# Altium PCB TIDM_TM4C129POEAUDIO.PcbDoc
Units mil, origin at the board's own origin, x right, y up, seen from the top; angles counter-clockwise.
Board outline 2400 x 2000 mil, 4 copper layers (Component Side, Ground Plane, Power Plane, Solder Side), stack 33.234 mil thick; 37 components, 28 nets, 131 pads, 28 vias.
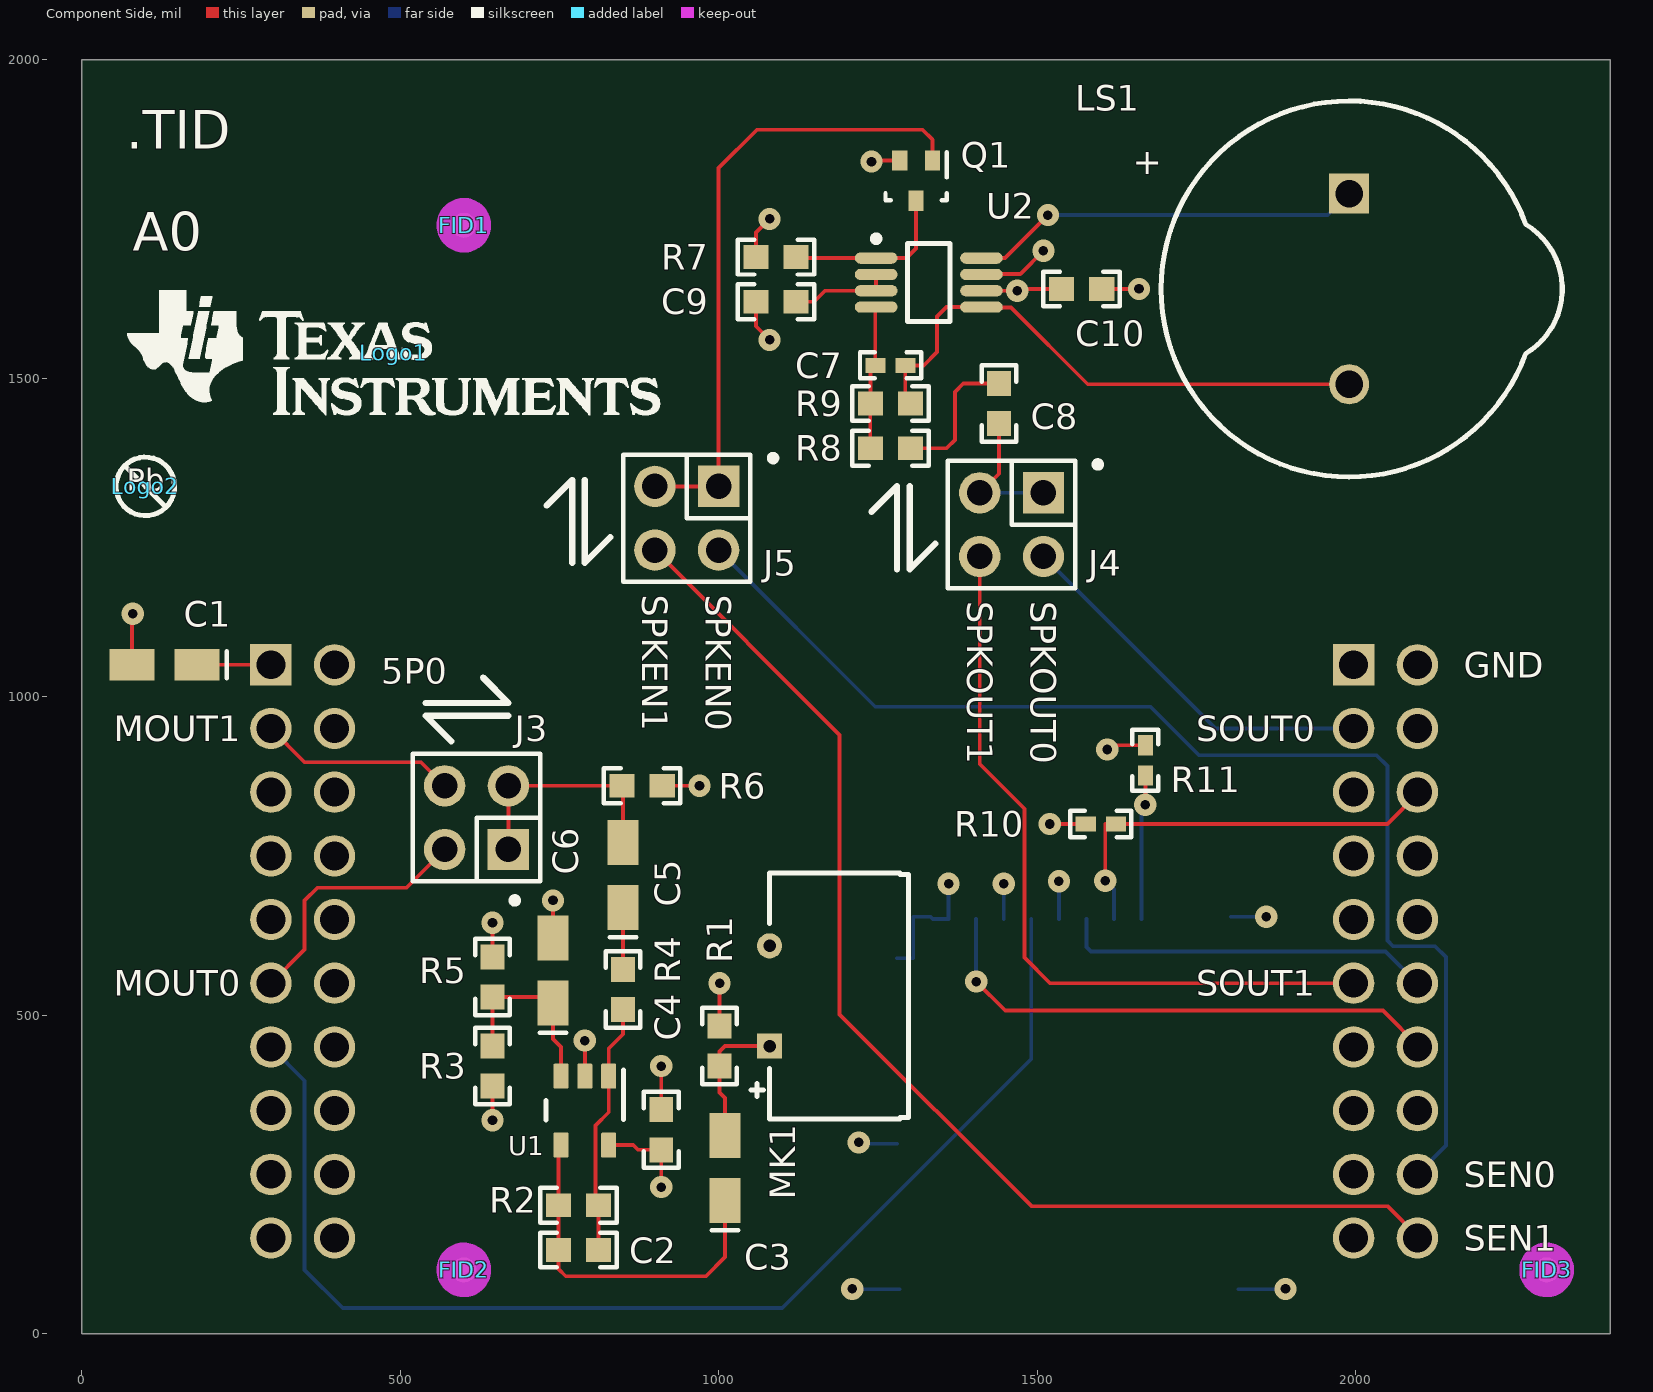
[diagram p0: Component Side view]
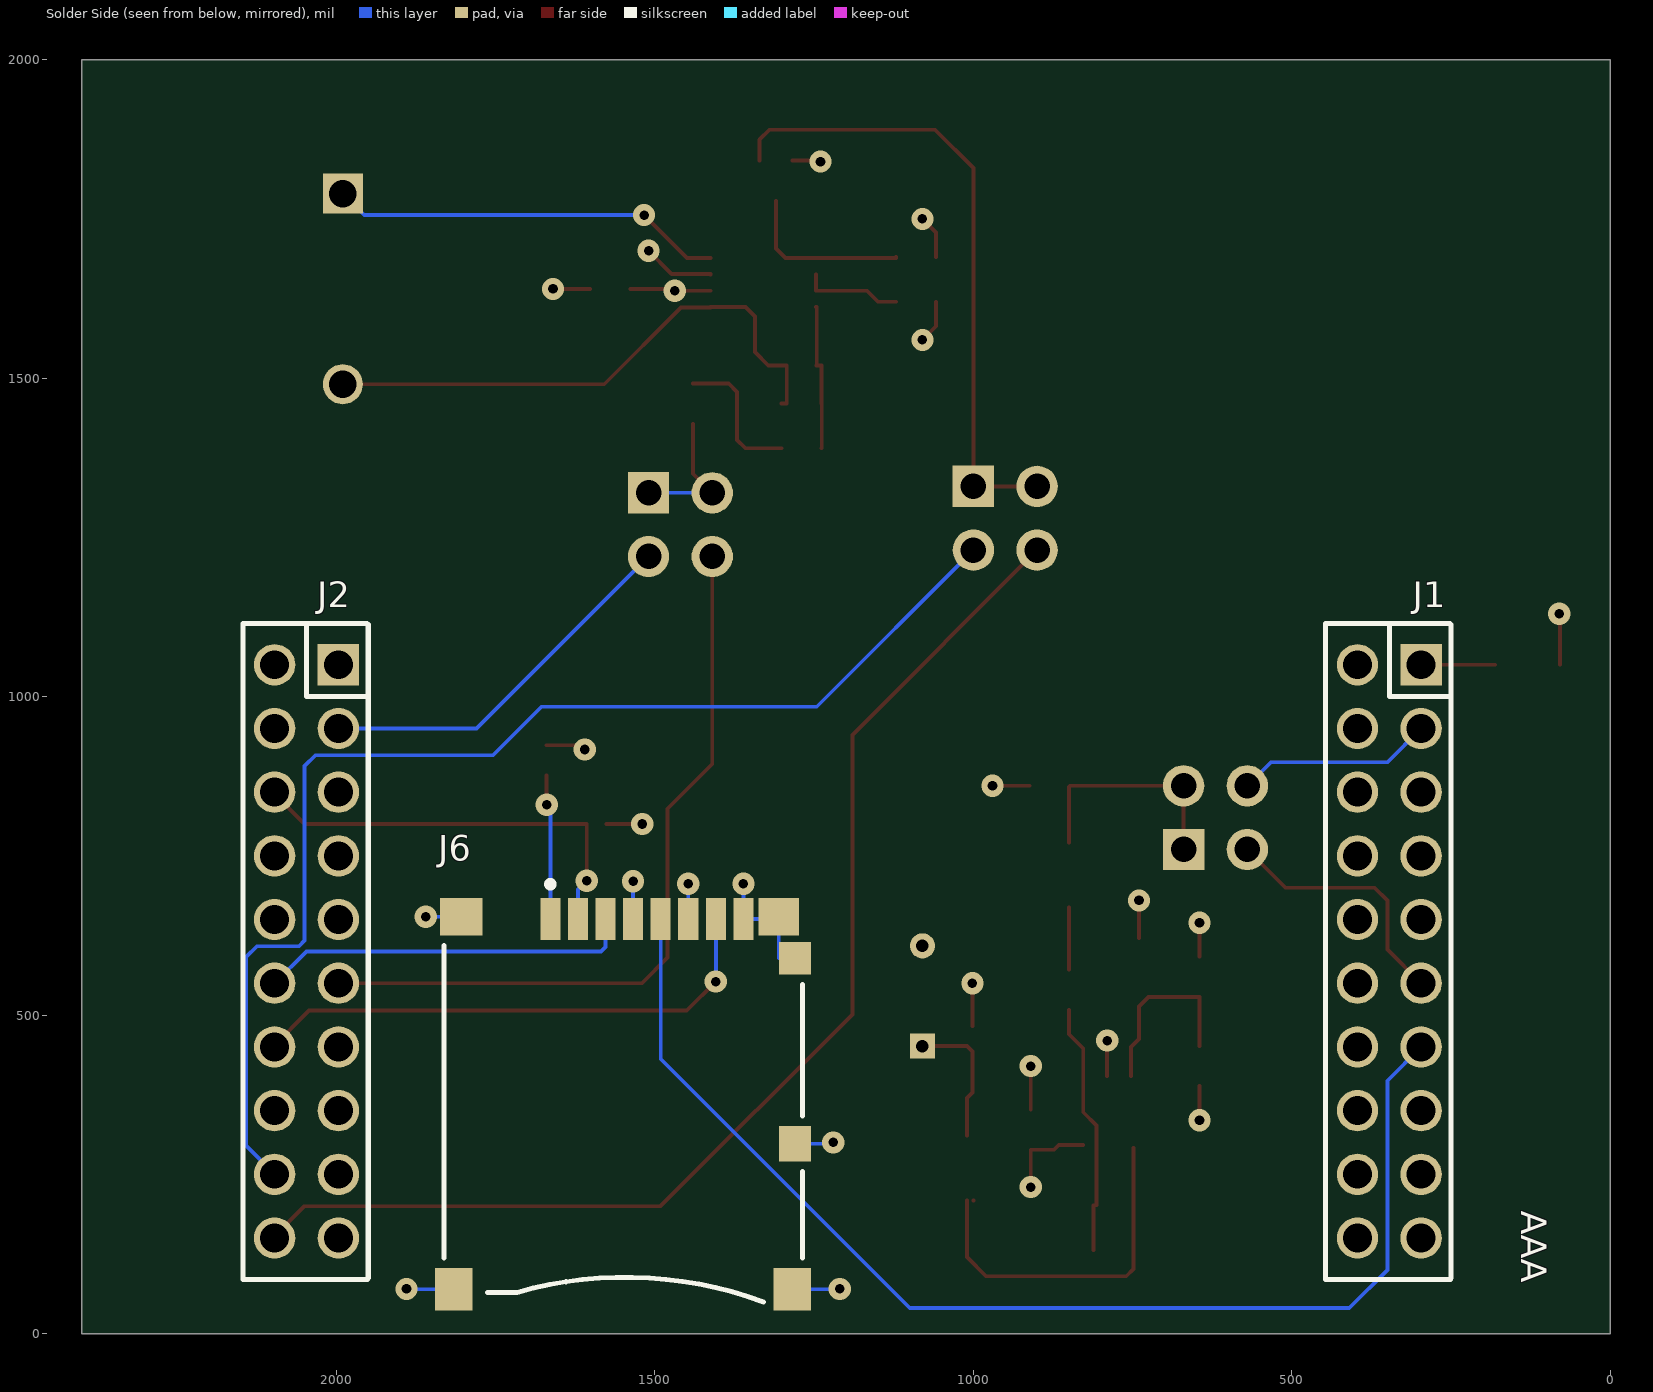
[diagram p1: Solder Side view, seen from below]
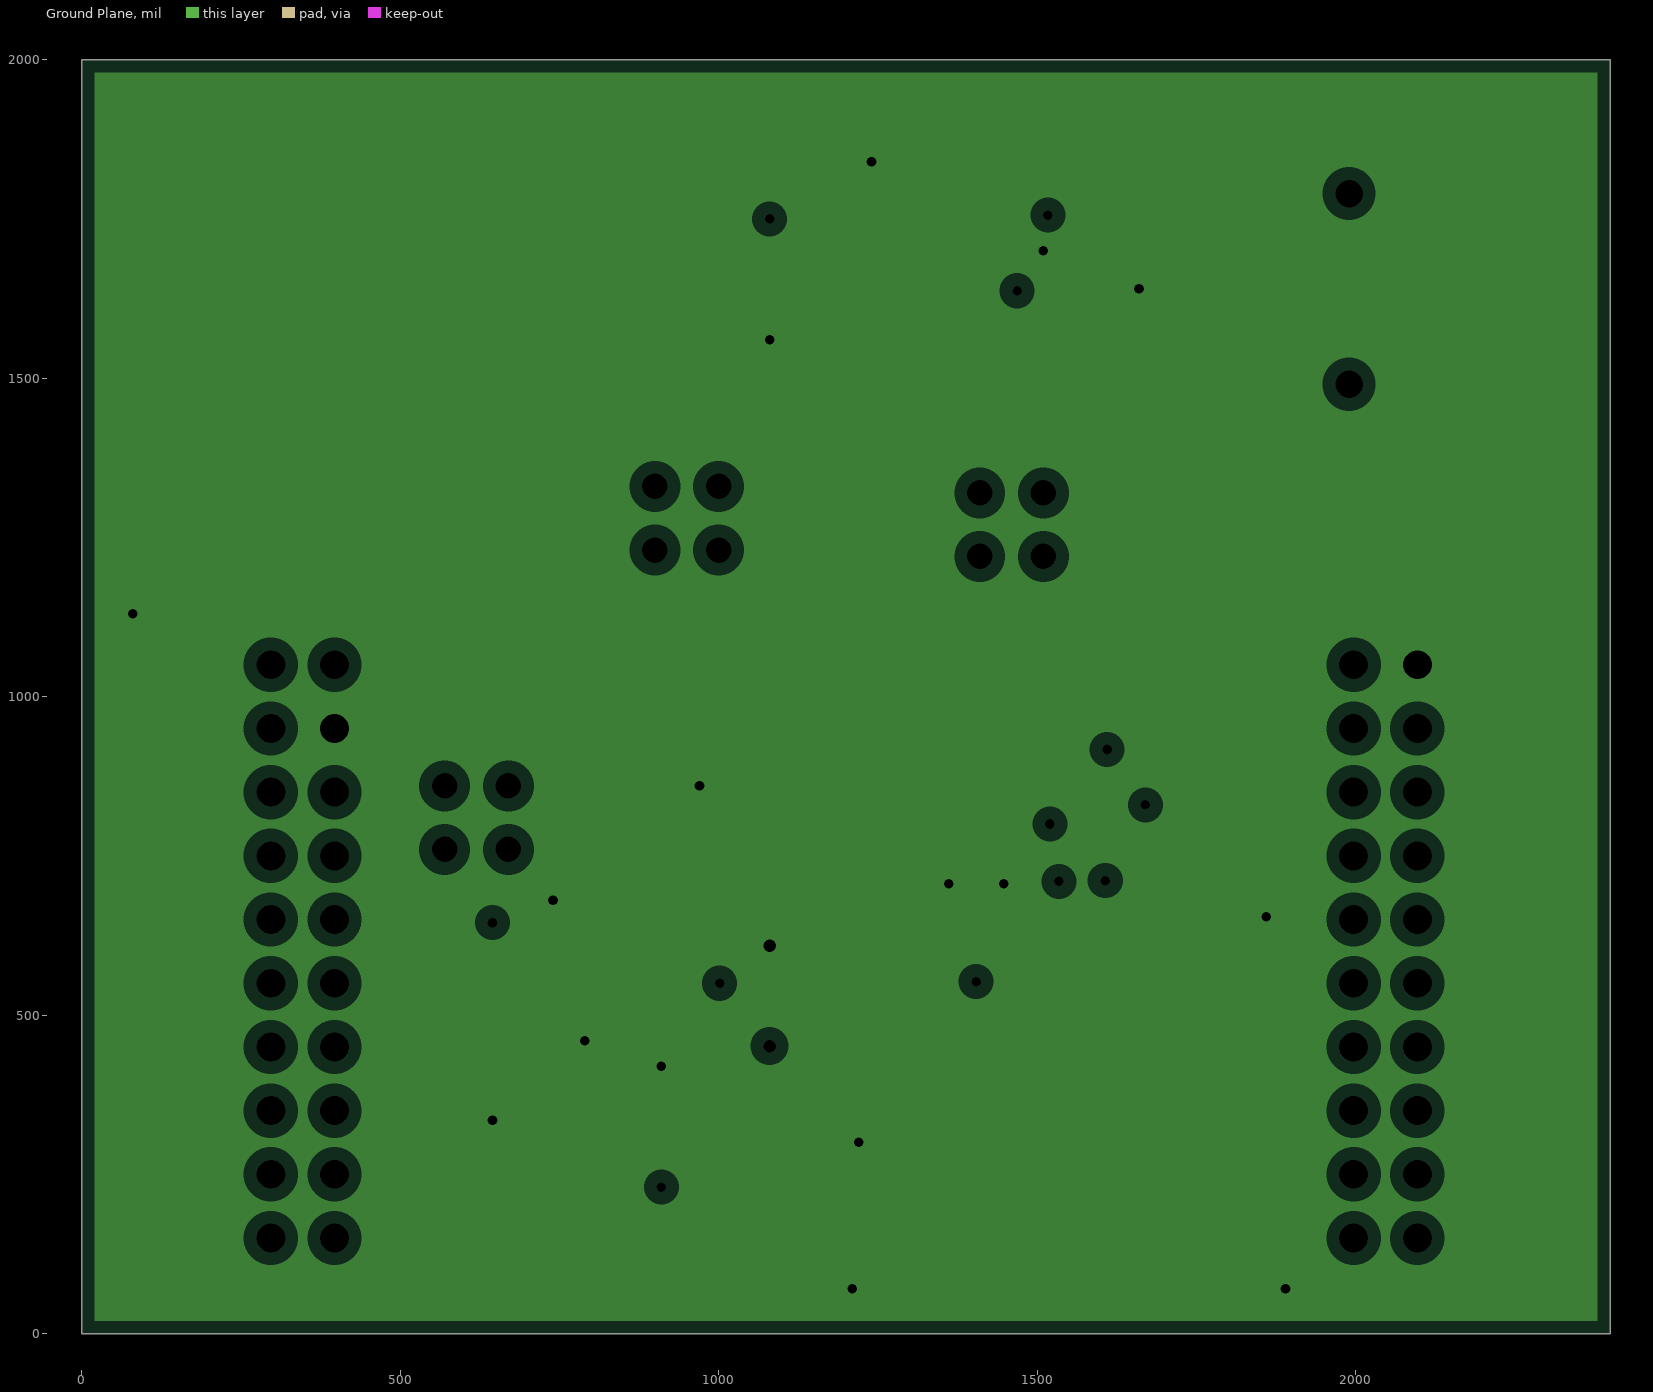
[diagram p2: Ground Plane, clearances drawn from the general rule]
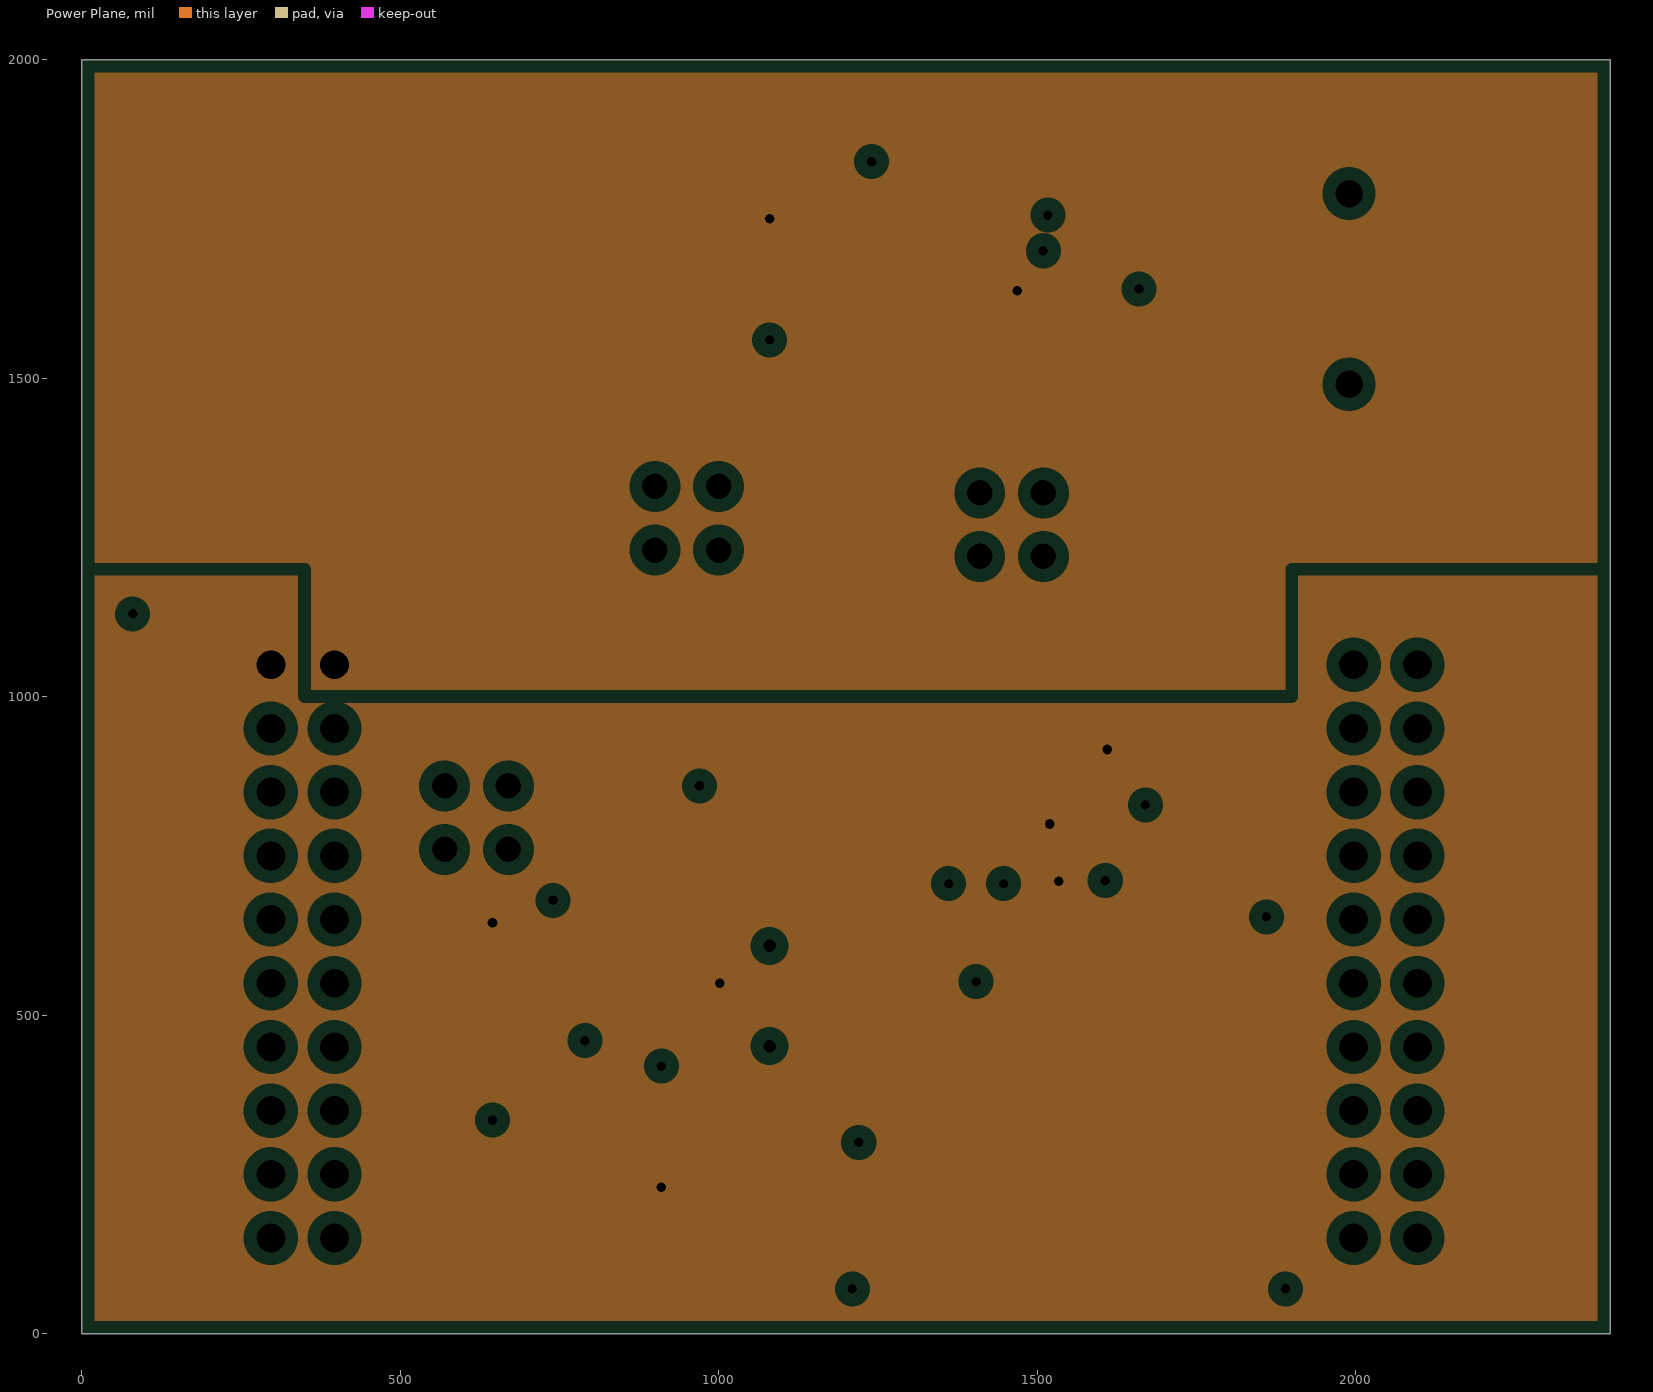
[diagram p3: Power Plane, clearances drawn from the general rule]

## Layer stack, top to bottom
Top Solder: solder mask 0.4, Solder Resist, Dk 3.5
Component Side: signal copper 1.4
Dielectric 1: core 12.6, FR-4, Dk 4.8
Ground Plane: plane copper 1.417, net GND
Dielectric 3: prepreg 5, Dk 4.2
Power Plane: plane copper 1.417, net (Multiple Nets)
Dielectric 4: core 10, Dk 4.2
Solder Side: signal copper 1.4
Bottom Solder: solder mask 0.4, Solder Resist, Dk 3.5

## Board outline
0,0 0,2000 2400,2000 2400,0

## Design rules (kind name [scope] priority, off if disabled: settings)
AcuteAngle [All] p1: minimum=4.50000000000000E+0001 checktracksonly=FALSE
AssemblyTestPointUsage [All] p1: valid=2
Clearance Clearance_Keepouts [((IsTrack Or IsArc) And Not InPoly) And IsFree and IsKeepOut vs ((IsTrack Or IsArc) And Not InPoly) And IsFree and IsKeepOut] p1: gap=10
Clearance Clearance_BoardEdge_MountingHoles [OnCopper and InComponentClass('Mounting Holes') vs IsKeepOut] p2: gap=10
Clearance Clearance_BoardEdge_Poly [OnCopper and InPoly vs IsKeepOut] p3: gap=25
Clearance Clearance_BoardEdge [OnCopper and Not InComponentClass('Logo') and not InComponentClass('FiducialMark') and not InRegion(1000,500,4000,800) and Not IsKeepout vs IsKeepOut] p4: gap=75
Clearance Clearance_Poly [InPolygon] p5: gap=10
Clearance [All] p6: gap=6
ComponentClearance ComponentClearance_MountingHoles_FiducialMarks [InComponentClass('Mounting Holes') vs InComponentClass('FiducialMark')] p1: gap=50 collisioncheckmode=3 verticalgap=10 showdistances=FALSE
ComponentClearance ComponentClearance_Shunt [InComponentClass('Header') vs InComponentClass('Shunt')] p2: gap=0 collisioncheckmode=3 verticalgap=0 showdistances=FALSE
ComponentClearance ComponentClearance_Logo [InComponentClass('Logo')] p3: gap=50 collisioncheckmode=3 verticalgap=10 showdistances=FALSE
ComponentClearance ComponentClearance_ScrewToNut [(HasFootprint('NY PMS 440 0025 PH')) vs (HasFootprint('Keystone_1902C'))] p4: gap=5 collisioncheckmode=3 verticalgap=10 showdistances=FALSE
ComponentClearance ComponentClearance_MountingHoles [InComponentClass('Mounting Holes')] p5: gap=250 collisioncheckmode=3 verticalgap=100000 showdistances=FALSE
ComponentClearance ComponentClearance_SmallPassives [HasFootprint('0201*') or HasFootprint('0402*') or HasFootprint('0508') or HasFootprint('0603*') or HasFootprint('0612') or HasFootprint('0805*') or HasFootprint('0815*') or HasFootprint('0830*') or HasFootprint('1206*') or HasFootprint('1210*') or HasFootprint('1808*') or HasFootprint('1812*') or HasFootprint('1825*') or HasFootprint('2010*') or HasFootprint('2220*') or HasFootprint('2225*') or HasFootprint('2512*') or HasFootprint('2728*') or HasFootprint('3518*') vs HasFootprint('0201*') or HasFootprint('0402*') or HasFootprint('0508') or HasFootprint('0603*') or HasFootprint('0612') or HasFootprint('0805*') or HasFootprint('0815*') or HasFootprint('0830*') or HasFootprint('1206*') or HasFootprint('1210*') or HasFootprint('1808*') or HasFootprint('1812*') or HasFootprint('1825*') or HasFootprint('2010*') or HasFootprint('2220*') or HasFootprint('2225*') or HasFootprint('2512*') or HasFootprint('2728*') or HasFootprint('3518*')] p6: gap=20 collisioncheckmode=3 verticalgap=10 showdistances=FALSE
ComponentClearance ComponentClearance_THtoSMT [IsThruComponent vs IsSMTComponent] p7: gap=50 collisioncheckmode=3 verticalgap=30 showdistances=FALSE
ComponentClearance ComponentClearance_THtoTH [IsThruComponent vs IsThruComponent] p8: gap=50 collisioncheckmode=3 verticalgap=30 showdistances=FALSE
ComponentClearance [All] p9: gap=39 collisioncheckmode=3 verticalgap=10 showdistances=FALSE
DiffPairsRouting [All] p1: maxlimit=100 minlimit=10 mostfreqgap=10 toplayer_minwidth=15 toplayer_maxwidth=15 toplayer_prefwidth=15 bottomlayer_minwidth=15 bottomlayer_maxwidth=15 bottomlayer_prefwidth=15 maxuncoupledlength=1000
FabricationTestPointUsage TestPointUsage [All] p1: valid=2 allowmultiple=FALSE
FabricationTestpoint Testpoint [All] p1: side=3 testpointundercomponent=TRUE minsize=40 maxsize=100 preferedsize=60 minholesize=0 maxholesize=40 preferedholesize=32 testpointgrid=1 allowsidetop=TRUE allowsidebottom=TRUE usegrid=TRUE gridtolerance=0.01
FanoutControl Fanout_LCC [IsLCC] p1: bgadir=Out bgaviamode=Centered fanoutstyle=Auto fanoutdirection=Alternating viagrid=1 // Fanout_LCC (Default Rule)
FanoutControl Fanout_BGA [IsBGA] p2: bgadir=Out bgaviamode=Centered fanoutstyle=Auto fanoutdirection=Alternating viagrid=1 // Fanout_BGA (Default Rule)
FanoutControl Fanout_Default [All] p4: bgadir=Out bgaviamode=Centered fanoutstyle=Auto fanoutdirection=Alternating viagrid=1 // Fanout_Default (Default Rule)
FanoutControl Fanout_Small [(CompPinCount < 5)] p5: bgadir=Out bgaviamode=Centered fanoutstyle=Auto fanoutdirection=OutThenIn viagrid=1 // Fanout_Small (Default Rule)
HoleSize [All] p1: absolutevalues=TRUE maxlimit=251 minlimit=8 maxpercent=80.000 minpercent=20.000
MinimumAnnularRing MinimumAnnularRing_ThermalPadVias [IsVia and InAnyComponent] p1: minimumring=5.91
MinimumAnnularRing [All] p2: minimumring=6
MinimumSolderMaskSliver MinimumSolderMaskSliver_Logo [InComponentClass('Logo') vs InComponentClass('Logo')] p1: minsoldermaskwidth=0.7
MinimumSolderMaskSliver [All] p2: minsoldermaskwidth=3.94
PlaneClearance [All] p1: clearance=20
PlaneConnect [All] p1: planeconnectstyle=Relief reliefexpansion=13 reliefentries=4 reliefconductorwidth=10 reliefairgap=10
PolygonConnect [All] p1: connectstyle=Relief reliefconductorwidth=10 reliefentries=4 polygonreliefangle="90 Angle" airgapwidth=10
RoutingVias ThermalPadVias [IsVia and InAnyComponent] p1: holewidth=7.87 width=19.68 viastyle="Through Hole" minholewidth=7.87 minwidth=19.68 maxholewidth=12.99 maxwidth=23.62
RoutingVias [All] p2: holewidth=15 width=35 viastyle="Through Hole" minholewidth=10 minwidth=30 maxholewidth=15 maxwidth=35
SMDNeckDown [All] p1: percent=60.000
SilkToBoardRegionClearance [Not ((IsComment or IsDesignator) And (Hide <> 'False')) and not InRegion(1000,500,4000,800)] p1:
SilkToSilkClearance SilkToSilkClearance_Pb-FreeLogo [(HasFootprint('Pb-Free_Overlay_Medium') OR HasFootprint('Pb-Free_Overlay_Small')) vs (HasFootprint('Pb-Free_Overlay_Medium') OR HasFootprint('Pb-Free_Overlay_Small'))] p1: silktosilkclearance=0
SilkToSilkClearance [All] p2: silktosilkclearance=4
SilkToSolderMaskClearance SilkToComonentPadClearance [IsPad and InAnycomponent] p1: minsilkscreentomaskgap=5 clearancetoexposedcopper=TRUE
SilkToSolderMaskClearance "Silk to Solder Mask Opening" [All] p2: minsilkscreentomaskgap=4 clearancetoexposedcopper=FALSE
SolderMaskExpansion SolderMaskExpansion_1 [IsVia] p1: expansion=-20
SolderMaskExpansion [All] p2: expansion=1.97
UnpouredPolygon [All] p1: allowunpoured=FALSE
Width [All] p1: maxlimit=100 minlimit=6 preferedwidth=6 checkconnectedcopper=TRUE
13 further rules are at their usual default settings.

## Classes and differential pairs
component class Header: J3 J4 J5
component class Logo: Logo1
component class FiducialMark: FID1 FID2 FID3

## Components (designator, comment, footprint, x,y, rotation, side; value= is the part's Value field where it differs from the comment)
C1 "TPSA225K010R1800" 3216-18 130,1050 r180 top
C2 "GRM1885C1H160JA01D" 0603 780,131.32 r180 top
C3 "T495A685K010ZTE1K8" 3216-18 1010,260 r90 top
C4 "0603YC104JAT2A" 0603 910,320 r90 top
C5 "TPSA225K010R1800" 3216-18 850,720 r90 top
C6 "TPSA225K010R1800" 3216-18 740,570 r90 top
C7 "GRM1555C1H751JA01D" 0402 1270,1520 r180 top
C8 "GRM188R71C473KA01D" 0603 1440,1460 r270 top
C9 "GRM188R71A474KA61D" 0603 1090,1620 r180 top
C10 "GRM188R71E105KA12D" 0603 1570,1640 r0 top
FID1 "Fiducial" Fiducial10-20 600,1740 r0 top
FID2 "Fiducial" Fiducial10-20 600,100 r0 top
FID3 "Fiducial" Fiducial10-20 2300,100 r0 top
J1 "SSW-110-23-F-D" CONN_SSW-110-23-F-D 347,600 r90 bottom
J2 "SSW-110-23-F-D" CONN_SSW-110-23-F-D 2047,600 r90 bottom
J3 "TSW-102-07-G-D" TSW-102-07-G-D 620,810 r90 top
J4 "TSW-102-07-G-D" TSW-102-07-G-D 1460,1270 r180 top
J5 "TSW-102-07-G-D" TSW-102-07-G-D 950,1280 r180 top
J6 "502774-0891" Molex_502774-0891 1550,360 r180 bottom
Logo1 "Texas Instruments" TI_Stacked_Overlay_Small 490,1540 r0 top
Logo2 "Pb-Free Symbol" Pb-Free_Overlay_Small 100,1330 r0 top
LS1 "CVS-1508" CUI_CVS-1508 1990,1640 r0 top
MK1 "AUM-5047L-3-LW100-R" PUI_AUM 1080,530 r90 top
Q1 "DTC114EUAT106" SOT-323 1310,1810 r270 top
R1 "RC0603FR-073K6L" 0603 1001.5,451.26 r90 top
R2 "CRCW060393K1FKEA" 0603 780,201.32 r0 top
R3 "RC0603FR-07100KL" 0603 645,420 r90 top
R4 "RC0603FR-0749R9L" 0603 850,540 r90 top
R5 "RC0603FR-07100KL" 0603 645,560 r90 top
R6 "RC0603FR-07100KL" 0603 880,860 r180 top
R7 "RC0603FR-0710KL" 0603 1090,1690 r180 top
R8 "RC0603FR-0720KL" 0603 1270,1390 r180 top
R9 "RC0603FR-0720KL" 0603 1270,1460 r0 top
R10 "CRCW040210K0FKED" 0402 1600,800 r0 top
R11 "CRCW040210K0FKED" 0402 1670,900 r270 top
U1 "OPA322AIDBVR" DBV0005A_N 790,350 r270 top
U2 "LM4819MM" MUA08A_N 1330,1650 r0 top

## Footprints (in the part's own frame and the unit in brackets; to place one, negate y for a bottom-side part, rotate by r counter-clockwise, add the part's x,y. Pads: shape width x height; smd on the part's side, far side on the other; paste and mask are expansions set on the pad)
0402 [mm] "0402 from SM-752 data"
  rect 0.8x0.6 smd: 1(-0.6,0) 2(0.6,0)
  silkscreen extent -1.22,-0.52 1.22,0.52, body extent -0.55,-0.3 0.55,0.3, height 0.6
0603 [mm] "0603 from SM-752 data"
  rect 1x0.95 smd: 1(-0.8,0) 2(0.8,0)
  silkscreen extent -1.52,-0.69 1.52,0.69, body extent -0.87,-0.47 0.87,0.47, height 1
3216-18 [mm] "Medium density IPC, based on Kemet T495 dimensions"
  rect 1.8x1.25 smd: 1(-1.3,0) 2(1.3,0)
  silkscreen extent -2.49,-0.54 -2.49,0.54, body extent -1.7,-0.9 1.7,0.9, height 1.8
CONN_SSW-110-23-F-D [mm] "SAMTEC"
  rect 1.65x1.65 hole 1.15: 1(11.43,-1.27)
  round 1.65 hole 1.15: 2(11.43,1.27) 3(8.89,-1.27) 4(8.89,1.27) 5(6.35,-1.27) 6(6.35,1.27) 7(3.81,-1.27) 8(3.81,1.27) 9(1.27,-1.27) 10(1.27,1.27) 11(-1.27,-1.27) 12(-1.27,1.27) 13(-3.81,-1.27) 14(-3.81,1.27) 15(-6.35,-1.27) 16(-6.35,1.27) 17(-8.89,-1.27) 18(-8.89,1.27) 19(-11.43,-1.27) 20(-11.43,1.27)
  silkscreen extent -13.08,-2.46 13.08,2.54, body extent -13,-2.51 13,2.54, height 8.59
CUI_CVS-1508 [mm] "Speaker, 2-Leads, Dia 15mm, Lead Spacing 7.6mm"
  rect 1.6x1.6 hole 1.1: 1(0,3.8)
  round 1.6 hole 1.1: 2(0,-3.8)
  silkscreen extent -7.5,-7.5 8.5,7.5, body extent -7.5,-7.5 8.5,7.5, height 7.6
DBV0005A_N [mm] "SOT23, 5-Leads, Body 2.9x1.6mm, Pitch 0.95mm, Lead Span 2.8mm, IPC Medium Density"
  rrect17% 1x0.6 smd: 1(-1.375,0.95) 2(-1.375,0) 3(-1.375,-0.95) 4(1.375,-0.95) 5(1.375,0.95)
  silkscreen extent -1.62,-1.55 0.38,1.55, body extent -1.42,-1.46 1.42,1.46, height 1.09
Fiducial10-20 [mm]
  round 1 smd mask+0.5: 1(0,0)
  Component Side keep-out circle w1.178: c0,0 r0.5
Molex_502774-0891 [mm] "SMD, 14-Leads, Body 15x14.3mm, Pitch 1.1mm"
  rect 0.8x1.68 smd: 1(-2.9,7.385) 2(-1.8,7.385) 3(-0.7,7.385) 4(0.4,7.385) 5(1.5,7.385) 6(2.6,7.385) 7(3.7,7.385) 8(4.8,7.385)
  rect 1.6x1.5 smd: 9(6.21,7.475)
  rect 1.29x1.3 smd: 10(6.855,5.825)
  rect 1.29x1.4 smd: 11(6.855,-1.575)
  rect 1.5x1.7 smd: 12(6.75,-7.375) 13(-6.75,-7.375)
  rect 1.7x1.5 smd: 14(-6.45,7.475)
  silkscreen extent -7.15,-7.88 7.15,8.9, body extent -7.15,-8 7.15,8, height 1.78
MUA08A_N [mm] "TSOP, 8-Leads, Body 3x3mm, Pitch 0.65mm, IPC Medium Density"
  oval 1.7x0.45 smd: 1(-2.1,0.975) 2(-2.1,0.325) 3(-2.1,-0.325) 4(-2.1,-0.975) 5(2.1,-0.975) 6(2.1,-0.325) 7(2.1,0.325) 8(2.1,0.975)
  silkscreen extent -2.22,-1.55 0.85,1.87, body extent -1.6,-1.6 1.6,1.6, height 1.09
Pb-Free_Overlay_Small [mil]
  silkscreen extent -46,-46 46,46
PUI_AUM [mm] "TH, 2-Leads, Dia 9.7mm"
  rect 1x1 hole 0.5: 1(-2,0)
  round 1 hole 0.5: 2(2,0)
  silkscreen extent -4.9,-5.55 4.9,0.75, body extent -4.86,-5.55 4.9,0.12, height 9.79
SOT-323 [mm] "Zetex recommended land pattern.  March 2007"
  rect 0.8x0.6 smd: 1(-0.8,0.65) 2(-0.8,-0.65) 3(0.8,0)
  silkscreen extent -1.14,-1.22 0.78,1.22, body extent -1.13,-1.13 1.12,1.12, height 1.13
TI_Stacked_Overlay_Small [mil]
  silkscreen extent -418,-98 418,98
TSW-102-07-G-D [mm] "Samtec 100mil, 2x2, 230 mil above insulator"
  rect 1.65x1.65 hole 1.016 mask+0: 1(-1.27,-1.27)
  round 1.65 hole 1.016 mask+0: 2(-1.27,1.27) 3(1.27,-1.27) 4(1.27,1.27)
  silkscreen extent -3.43,-2.54 2.54,2.54, body extent -2.54,-2.54 2.54,2.54, height 8.38

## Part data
C1 C5 C6: "CAP, TA, 2.2 µF, 10 V, +/- 10%, 1.8 ohm, SMD"
C2: "CAP, CERM, 16 pF, 50 V, +/- 5%, C0G/NP0, 0603"
C3: "CAP, TA, 6.8 µF, 10 V, +/- 10%, 1.8 ohm, SMD"
C4: "CAP, CERM, 0.1 µF, 16 V, +/- 5%, X7R, 0603"
C7: "CAP, CERM, 750 pF, 50 V, +/- 5%, C0G/NP0, 0402"
C8: "CAP, CERM, 0.047 µF, 16 V, +/- 10%, X7R, 0603"
C9: "CAP, CERM, 0.47 µF, 10 V, +/- 10%, X7R, 0603"
C10: "CAP, CERM, 1 µF, 25 V, +/- 10%, X7R, 0603"
FID1 FID2 FID3: "Fiducial mark.  There is nothing to buy or mount."
J1 J2: "Connector, Receptacle, 100mil, 10x2, Gold plated, TH"
J3 J4 J5: "Header, 100mil, 2x2, Gold, TH"
J6: "Conncetor, micro SD Card, 1.1 mm, R/A, SMT"
Logo1: library part TI_Logo, "Texas Instrument Corporate Signature"
Logo2: library part Pb-Free
LS1: "Speaker, 8Ohms, 0.3W, 15mm Round, TH"
MK1: "Microphone, TH"
Q1: library part "DTC114EUAT106, Rohm", "Transistor, NPN, 50 V, 0.05 A, SOT-323"
R1: "RES, 3.60 k, 1%, 0.1 W, 0603"
R2: "RES, 93.1 k, 1%, 0.1 W, 0603"
R3 R5 R6: "RES, 100 k, 1%, 0.1 W, 0603"
R4: "RES, 49.9, 1%, 0.1 W, 0603"
R7: "RES, 10.0 k, 1%, 0.1 W, 0603"
R8 R9: "RES, 20.0 k, 1%, 0.1 W, 0603"
R10 R11: "RES, 10.0 k, 1%, 0.063 W, 0402"
U1: "20 MHz, Low Noise, RRIO, CMOS Operational Amplifier with Shutdown, 1.8 to 5.5 V, -40 to 125 degC, 5-pin SOT23 (DBV0005A), Green (RoHS & no Sb/Br)"
U2: "350mW Audio Power Amplifier with Shutdown Mode, 8-pin Mini SOIC"

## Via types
v1: diameter 35, hole 15, Component Side to Solder Side, 28 vias

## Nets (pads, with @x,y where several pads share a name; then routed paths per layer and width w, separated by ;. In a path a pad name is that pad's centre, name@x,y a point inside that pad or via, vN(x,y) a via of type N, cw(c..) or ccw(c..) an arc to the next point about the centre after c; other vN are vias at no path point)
GND: C1.2 C4.2 C6.2 C9.2 C10.2 J1.4 J2.2 J6.6 J6.8 J6.9 J6.10 J6.11 J6.12 J6.13 J6.14 MK1.2 Q1.2 R3.1 R6.1 U1.2 U2.7 | length 1182.2
  Component Side w6: C1.2 78.82,1128.82 v1(80,1130) ; v1(645,335) R3.1 ; C6.2 v1(740,680) ; U1.2 v1(790,460) ; C4.2 v1(910,420) ; R6.1 v1(970,860) ; C9.2 1058.5,1581.5 v1(1080,1560) ; v1(1240,1840) 1241.5,1841.5 Q1.2 ; U2.7 1412.68,1663.7 1473.7,1663.7 v1(1510,1700) ; C10.2 v1(1660,1640)
  Solder Side w6: v1@1210.35,69.65 J6.12 ; v1@1222.01,297.99 J6.11 ; J6.10 1305.51,589.33 J6.9 1332.71,654.29 1336.25,650.75 J6.8 v1(1361.02,706.32) ; J6.6 v1(1447.64,706.32) ; J6.14 v1(1859.9,654.29) ; J6.13 1889.65,69.65 v1(1890,70)
  other v1: 1210,70 1220,300
MICOUT0: J1.11 J3.2 | length 407.2
  Component Side w6: J1.11 350,603 350,680 370,700 510,700 J3.2
  Solder Side w6: J1.11@298.5,551.5 J1.11@300,550
MICOUT1: J1.3 J3.4 | length 620.6
  Component Side w6: J1.3 350,897 533,897 J3.4
  Solder Side w6: J1.3 350,897 533,897 J3.4
MICOUT_S: C5.2 J3.1 J3.3 R6.2 | length 367.9
  Component Side w6: J3.1 670,771.18 J3.3 R6.2 850,858.5 C5.2
NetC2_1: C2.1 R2.2 R4.1 U1.1 | length 400.1
  Component Side w6: C2.1 R2.2 806.59,201.32 806.59,326.59 827.4,347.4 U1.1 827.4,447.4 850,470 R4.1
NetC2_2: C2.2 C3.1 R2.1 U1.4 | length 557.8
  Component Side w6: U1.4@748.5,291.77 C2.2 748.5,101.5 760,90 980,90 1010,120 C3.1
NetC3_2: C3.2 MK1.1 R1.1 | length 217.1
  Component Side w6: C3.2 1010,369.84 1001.5,378.35 R1.1 1001.5,442.76 1010,451.26 MK1.1
NetC5_1: C5.1 R4.2 | length 97.3
  Component Side w6: R4.2 C5.1
NetC6_1: C6.1 R3.2 R5.1 U1.3 | length 292.8
  Component Side w6: R3.2 R5.1 724.9,528.5 740,513.41 740,462.6 752.6,450 U1.3
NetC7_1: C7.1 LS1.2 R9.2 U2.5 | length 886.8
  Component Side w6: R9.2 1293,1460 1293,1520 C7.1 1322,1520 1343,1541 1343,1596.61 1358,1611.61 U2.5 1412.68,1610.7 1459.3,1610.7 1579.61,1490.39 LS1.2
NetC7_2: C7.2 R8.2 R9.1 U2.4 | length 231.8
  Component Side w6: R8.2 1238,1390 1238,1460 R9.1 1238.5,1520 C7.2@1246,1520 ; C7.2 C7.2@1246,1520 ; U2.4 1246,1611.61 C7.2@1246,1520
NetC8_1: C8.1 R8.1 | length 224.8
  Component Side w6: R8.1 1358,1390 1371,1403 1371,1478.5 1384,1491.5 C8.1
NetC9_1: C9.1 U2.2 U2.3 | length 158.9
  Component Side w6: C9.1 1149.8,1620 1167,1637.2 U2.3@1247,1637.2 ; U2.3 U2.3@1247,1637.2 ; U2.2 1247,1662.8 U2.3@1247,1637.2
NetJ6_1: J6.1 R11.2 | length 228
  Component Side w6: v1(1670,830) R11.2
  Solder Side w6: J6.1 1664.17,824.17 v1(1670,830)
NetLS1_1: LS1.1 U2.8 | length 619.2
  Component Side w6: U2.8 1449.39,1688.39 v1(1517,1756)
  Solder Side w6: v1(1517,1756) 1956.39,1756 LS1.1
NetQ1_3: Q1.3 R7.1 U2.1 | length 271.4
  Component Side w6: R7.1 1121.5,1688.39 U2.1 1294.92,1688.39 1310,1703.46 Q1.3
SD_CLK: J1.13 J6.5 | length 1919.5
  Solder Side w6: J1.13 350,397 350,100 410,40 1100,40 1490.94,430.94 J6.5
SD_CS: J2.6 J6.2 R10.2 | length 668.4
  Component Side w6: v1(1607,711) 1607,799.5 1607.5,800 R10.2 2050,800 J2.6@2100,850
  Solder Side w6: v1(1607,711) 1620.87,697.13 J6.2
SD_RDAT: J2.14 J6.7 | length 836.3
  Component Side w6: v1(1404.33,552.67) 1450,507 2043,507 J2.14@2100,450
  Solder Side w6: v1(1404.33,552.67) J6.7
SD_WDAT: J2.12 J6.3 | length 588.9
  Solder Side w6: J6.3 1577.56,607 1584.56,600 2047,600 J2.12 ; J2.12@2098.5,551.5 J2.12@2100,550
SPKEN0: J2.18 J5.2 | length 1926.8
  Solder Side w6: J5.2 1246,984 1678,984 1754,908 2033,908 2050,891 2050,617 2059,608 2125,608 2142,591 2142,295 J2.18
SPKEN1: J2.20 J5.4 | length 1904.5
  Component Side w6: J5.4 1190,940 1190,501 1491,200 2050,200 J2.20@2100,150
SPKEN_S: J5.1 J5.3 Q1.1 | length 999.8
  Component Side w6: J5.3 J5.1 1000,1830 1060,1890 1320,1890 1335.59,1874.41 Q1.1
SPKOUT0: J2.3 J4.2 | length 601.8
  Solder Side w6: J4.2 1780,950 J2.3 J2.3@2000,950
SPKOUT1: J2.11 J4.4 | length 1195.3
  Component Side w6: J4.4 1410,894 1480,824 1480,590.5 1520.5,550 J2.11 J2.11@2000,550
SPKOUT_S: C8.2 J4.1 J4.3 | length 220.9
  Component Side w6: J4.3 1440,1350 C8.2
  Solder Side w6: J4.3 J4.1
VCC_3P3: C1.1 C4.1 J1.1 J6.4 R1.2 R5.2 R10.1 R11.1 U1.5 | length 562.1
  Component Side w6: C1.1 J1.1 J1.1@300,1050 ; R5.2 v1(645,645) ; U1.5 865.87,295.87 873.23,288.5 C4.1 v1(910,230) ; R1.2 v1(1001.5,550) ; v1(1520,800) R10.1 ; v1(1610,917) 1616.62,923.62 R11.1
  Solder Side w6: J6.4 v1(1534.25,710)
VCC_5P0: C10.1 J1.2 R7.2 U2.6 | length 198.3
  Component Side w6: R7.2 1058.5,1728.5 v1(1080,1750) ; U2.6 v1@1466.2,1637.2 ; v1(1468.64,1637.2) v1@1466.2,1637.2 ; C10.1 1469,1640 v1@1466.2,1637.2
pads on no net: FID1.1 FID2.1 FID3.1 J1.5 J1.6 J1.7 J1.8 J1.9 J1.10 J1.12 J1.14 J1.15 J1.16 J1.17 J1.18 J1.19 J1.20 J2.1 J2.4 J2.5 J2.7 J2.8 J2.9 J2.10 J2.13 J2.15 J2.16 J2.17 J2.19

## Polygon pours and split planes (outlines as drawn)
GND on Ground Plane (split plane): 2379.9,20.1 20.1,20.1 20.1,1979.9 2379.9,1979.9
VCC_5P0 on Power Plane (split plane): 2379.9,1210.09 1900,1210.09 1897.39,1209.74 1894.96,1208.74 1892.87,1207.13 1891.26,1205.04 1890.26,1202.61 1889.91,1200 1889.91,1010.09 360.09,1010.09 360.09,1200 359.74,1202.61 358.73,1205.04 357.13,1207.13 355.04,1208.74 352.61,1209.74 350,1210.09 20.1,1210.09 20.1,1979.9 2379.9,1979.9
VCC_3P3 on Power Plane (split plane): 2379.9,20.1 20.1,20.1 20.1,1189.91 339.91,1189.91 339.91,1000 340.26,997.39 341.27,994.96 342.87,992.87 344.96,991.26 347.39,990.26 350,989.91 1900,989.91 1902.61,990.26 1905.04,991.26 1907.13,992.87 1908.74,994.96 1909.74,997.39 1910.09,1000 1910.09,1189.91 2379.9,1189.91

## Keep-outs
Keep-Out Layer:
  text ".Layer_Name" at 577,-858.49 h60

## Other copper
Component Side:
  text ".Layer_Name" at 577,-858.49 h60
Solder Side:
  text ".Layer_Name" at 577,-858.49 h60
Ground Plane (plane layer: these items are gaps in the copper):
  text ".Layer_Name" at 577,-858.49 h60
Power Plane (plane layer: these items are gaps in the copper):
  lines w20: 0,1200 350,1200 350,1000 1900,1000 1900,1200 2400,1200
  text ".Layer_Name" at 577,-858.49 h60

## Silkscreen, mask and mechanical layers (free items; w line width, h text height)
Top Overlay:
  lines w10: 540,990 670,990 630,1030 ; 580,930 540,970 670,970 ; 730,1300 770,1340 770,1210 ; 790,1340 790,1210 830,1250 ; 1240,1290 1280,1330 1280,1200 ; 1300,1330 1300,1200 1340,1240
  text ".TID" at 70,1860 h60
  text "A0" at 80,1700 h60
  text "SPKEN1" at 880,1160 h40 r270
  text "SPKEN0" at 980,1160 h40 r270
  text "SPKOUT1" at 1390,1150 h40 r270
  text "SPKOUT0" at 1490,1150 h40 r270
  text "GND" at 2170,1030 h40
  text "5P0" at 470,1020 h40
  text "MOUT1" at 50,930 h40
  text "SOUT0" at 1750,930 h40
  text "MOUT0" at 50,530 h40
  text "SOUT1" at 1750,530 h40
  text "SEN0" at 2170,230 h40
  text "SEN1" at 2170,130 h40
  text ".Layer_Name" at 577,-858.49 h60
Bottom Overlay:
  text "AAA" at 140,80 h40 r90
  text ".Layer_Name" at 577,-858.49 h60
Top Paste:
  text ".Layer_Name" at 577,-858.49 h60
Bottom Paste:
  text ".Layer_Name" at 577,-858.49 h60
Top Solder:
  text ".Layer_Name" at 577,-858.49 h60
  text ".Layer_Name" at 577,-858.49 h60
Bottom Solder:
  text ".Layer_Name" at 577,-858.49 h60
Drill Guide:
  text ".Layer_Name" at 577,-858.49 h60
Mechanical 1:
  lines w10: 2200,0 0,0 ; 0,0 0,1200 0,0 ; 0,0 2400,0 2400,2000 0,2000 0,0
Mechanical 2:
  rectangle: 0,-275 125,-150
  rectangle: 125,-400 500,-275
  lines w7: 0,-275 1000,-275 ; 125,-400 125,-150 ; 250,-400 250,-150 ; 500,-400 500,-150 ; 750,-400 750,-150 ; 0,-400 1000,-400 1000,-150 0,-150 0,-400
  lines w10: 0,2000 2400,2000 2400,0
  text ".Layer_Name" at 577,-858.49 h60
  text ".Layer_Name" at 577,-858.49 h60
Mechanical 3:
  text ".Layer_Name" at 577,-858.49 h60
  text ".Layer_Name" at 577,-858.49 h60
Mechanical 4:
  text ".Layer_Name" at 577,-858.49 h60
  text ".Layer_Name" at 577,-858.49 h60
Mechanical 5:
  lines w10: -292,-930.17 6308,-930.17 ; -292,-726.83 6310,-726.83 ; -292,-523.5 -292,-1133.5 3713,-1133.5 6310,-1133.5 6310,-523.5 -291.5,-523.5 -291.5,-1133.5 1284,-1133.5 ; 2173,-1133.5 2173,-523.5 ; 3440,-726.83 3440,-523.5 ; 4280,-726.83 4280,-523.5 ; 4902,-1140 4902,-937.17
  text "COMPONENTS MARKED 'DNP' SHOULD NOT BE POPULATED." at 1153.5,-318.5 h60
  text "ASSEMBLY VARIANT:" at 1153,-434 h60
  text ".VariantName" at 2189,-434 h60
  text "PCB VIEWED FROM TOP SIDE" at -228.5,-655.67 h60
  text "BOARD #:" at 2248,-655.67 h60
  text ".PRJ_Number" at 2793.5,-655.67 h60
  text "REV:" at 3638,-655.67 h60
  text ".PCB_Rev" at 3929.5,-655.67 h60
  text "SVN REV:" at 4476,-655.67 h60
  text ".VersionControl_RevNumber" at 4982,-655.67 h60
  text "LAYER NAME =" at -228.5,-858.49 h60
  text "TID #:" at 2248,-859 h60
  text ".TID" at 2793.5,-859 h60
  text "PLOT NAME =" at -228.5,-1064.34 h60
  text ".plot_File_Name" at 577,-1064.34 h60
  text "GENERATED    :" at 2250,-1064.34 h60
  text ".Print_Date" at 3119.5,-1064.34 h60
  text ".Print_Time" at 3848.5,-1064.34 h60
  text "TEXAS INSTRUMENTS" at 5113,-1064.34 h60
Mechanical 6:
  lines w10: -292.5,-727.33 6309.5,-727.33 ; -290.5,-930.67 6309.5,-930.67 ; 1115.5,-1140.5 1115.5,-937.67 ; 1737.5,-727.33 1737.5,-524 ; 2577.5,-727.33 2577.5,-524 ; 3844.5,-1134 3844.5,-524 ; 4733.5,-1134 6309,-1134 6309,-524 -292.5,-524 -292.5,-1134 2304.5,-1134 6309.5,-1134 6309.5,-524
  text "COMPONENTS MARKED 'DNP' SHOULD NOT BE POPULATED." at 6102,-318 h60
  text ".VariantName" at 5058,-434 h60
  text "ASSEMBLY VARIANT:" at 6097,-434 h60
  text ".VersionControl_RevNumber" at 1035.5,-656.17 h60
  text "SVN REV:" at 1541.5,-656.17 h60
  text ".PCB_Rev" at 2088,-656.17 h60
  text "REV:" at 2379.5,-656.17 h60
  text ".PRJ_Number" at 3224,-656.17 h60
  text "BOARD #:" at 3769.5,-656.17 h60
  text "PCB VIEWED FROM BOTTOM SIDE" at 6246,-656.17 h60
  text ".TID" at 3224,-859.5 h60
  text "TID #:" at 3769.5,-859.5 h60
  text "TEXAS INSTRUMENTS" at 904.5,-1064.84 h60
  text ".Print_Time" at 2169,-1064.84 h60
  text ".Print_Date" at 2898,-1064.84 h60
  text "GENERATED    :" at 3767.5,-1064.84 h60
  text ".plot_File_Name" at 5440.5,-1064.84 h60
  text "PLOT NAME =" at 6246,-1064.84 h60
Mechanical 9:
  drawing of 57 lines, arcs and shapes, not listed
  text "1" at 739.84,8036.5 h70
  text "2" at 3235.5,8036.5 h70
  text "3" at 5724.84,8036.5 h70
  text "4" at 8231.51,8036.5 h70
  text "5" at 10730.5,8036.5 h70
  text "6" at 13235.5,8036.5 h70
  text "A" at -416.5,6893.5 h70
  text "A" at 14383.5,6893.5 h70
  text "B" at -416.5,4513.5 h70
  text "B" at 14383.5,4513.5 h70
  text "C" at -416.5,2138.5 h70
  text "C" at 14383.5,2138.5 h70
  text "PROJECT TITLE:" at 11343.5,277.5 h45
  text ".PRJ_Title" at 11393.5,144.17 h70
  text "DESIGNED FOR:" at 11343.5,-23.5 h45
  text ".PRJ_Customer" at 11393.5,-163.5 h70
  text "D" at -416.5,-231.5 h70
  text "D" at 14383.5,-231.5 h70
  text "FILE NAME:" at 11343.5,-323.5 h45
  text ".PCB_File_Name_No_Path" at 11393.5,-443.5 h70
  text "Texas Instruments (TI) and/or its licensors do not warrant the accuracy or completeness of this specification" at 6374,-605.34 h45
  text "ENGINEER:" at 11343.5,-613.5 h45
  text "LAYOUT BY:" at 12848.5,-613.5 h45
  text "or any information contained therein. TI and/or its licensors do not warrant that this design will meet" at 6329.01,-718 h45
  text ".PRJ_Engineer" at 11393.5,-768.49 h70
  text ".PCB_Layout" at 12899,-768.49 h70
  text "the specifications, will be suitable for your application or fit for any particular purpose, or will operate in" at 6329.01,-830.67 h45
  text ".Layer_Name" at 577,-858.49 h60
  text "ALTIUM DESIGNER VERSION:" at 12848.5,-923.5 h45
  text "an implementation. TI and/or its licensors do not warrant that the design is production worthy. You should" at 6329.01,-943.33 h45
  text "completely validate and test your design implementation to confirm the system functionality for your application." at 6374,-1056 h45
  text ".print_Scale" at 11393.5,-1056.83 h70
  text ".Application_BuildNumber" at 12899,-1056.83 h70
  text "1" at 739.84,-1263.5 h70
  text "2" at 3235.5,-1263.5 h70
  text "3" at 5724.84,-1263.5 h70
  text "4" at 8231.51,-1263.5 h70
  text "5" at 10730.5,-1263.5 h70
  text "6" at 13235.5,-1263.5 h70
Mechanical 10:
  drawing of 173 lines, arcs and shapes, not listed
  text "DESIGN INFORMATION" at 12377.02,6201 h60
  text "MIN. TRACK WIDTH:" at 11732.46,6021 h60
  text "8" at 12828.7,6021 h60
  text "MIL" at 12983.46,6021 h60
  text "MIN. CLEARANCE:" at 11732.46,5889 h60
  text "0.2" at 12768.7,5889 h60
  text "mm" at 12983.46,5889 h60
  text "MIN. VIA PAD SIZE:" at 11732.46,5757 h60
  text "24" at 12798.71,5757 h60
  text "MIL" at 12983.46,5757 h60
  text "0.05mm (2MIL)" at 12427.46,5615.29 h60
  text "MINIMUM ANNULAR RING" at 11403.23,5611 h60
  text "EXTERNAL" at 13135.46,5611 h60
  text "PER" at 11603.23,5493 h60
  text "IPC-D-275 CLASS 2 LEVEL C" at 11823.23,5493 h60
  text "MIL, HOLES" at 13311.46,5380.71 h60
  text "+/-" at 12919,5380 h60
  text "+/-" at 13773,5380 h60
  text "REGISTRATION TOLERANCES:" at 11403.23,5375 h60
  text "METAL" at 12603,5375 h60
  text "5" at 13179.2,5375 h60
  text "3" at 14012.2,5375 h60
  text "MIL" at 14128.46,5375 h60
  text "+/-" at 13773,5262 h60
  text "HOLE SIZE TOLERANCE (UNLESS OTHERWISE SPECIFIED):" at 11403.23,5257 h60
  text "3" at 14012.2,5257 h60
  text "MIL" at 14128.46,5257 h60
  text "MATERIAL:" at 11328.46,5047.54 h60
  text "FR-4 High Tg" at 12314.9,4907.21 h60
  text "FR-408" at 11749.46,4898.64 h60
  text "OTHER" at 13237.46,4898.64 h60
  text "X" at 12160,4895 h60
  text "62 MIL (1.6mm) +/-10%" at 12069.56,4735.92 h60
  text "THICKNESS:" at 11403.23,4731.64 h60
  text "X" at 11941.4,4731.64 h60
  text "OTHER" at 13354.46,4731.64 h60
  text "TOLERANCE:" at 11403.23,4573.64 h60
  text "X" at 12242.53,4573.64 h60
  text "ANSI IPC-6012 TYPE 3 CLASS 2" at 12429.48,4573.64 h60
  text "OTHER +/-" at 12429.46,4417.64 h60
  text "BOW & TWIST:" at 11403.23,4260.64 h60
  text "X" at 12242.53,4260.64 h60
  text "ANSI IPC-6012 TYPE 3 CLASS 2" at 12429.48,4260.64 h60
  text "OTHER +/-" at 12429.46,4102.13 h60
  text "DRILLING:" at 11328.46,3963.64 h60
  text "REFERENCE:" at 11403.23,3846.64 h60
  text "X" at 12051.46,3846.64 h60
  text "AS SHOWN" at 12238.46,3846.64 h60
  text "X" at 12952.46,3846.64 h60
  text "NC_DRILL FILES" at 13089.46,3846.64 h60
  text "PTH MIN COPPER THICKNESS:" at 11403.23,3688.64 h60
  text "X" at 12753.46,3688.64 h60
  text "1MIL" at 12890.46,3688.64 h60
  text "OTHER" at 13387.46,3688.64 h60
  text "BOARD FINISH:" at 11328.46,3529.64 h60
  text "SILKSCREEN:" at 11483.68,3411.64 h60
  text "X" at 12432.46,3411.64 h60
  text "TOP" at 12558.46,3411.64 h60
  text "X" at 12942.46,3411.64 h60
  text "BOTTOM" at 13069.46,3411.64 h60
  text "SILKSCREEN COLOR:" at 11483.68,3244.64 h60
  text "X" at 12431.42,3244.64 h60
  text "WHITE" at 12558.46,3244.64 h60
  text "OTHER" at 13069.46,3244.64 h60
  text "X" at 12562.42,3085.44 h60
  text "GREEN" at 12689.46,3085.44 h60
  text "OTHER" at 13307.46,3085.44 h60
  text "SOLDER RESIST COLOR:" at 11483.68,3074.64 h60
  text "X" at 12562.42,2915.44 h60
  text "MATTE" at 12689.46,2915.44 h60
  text "SEMI-GLOSS" at 13307,2914.8 h60
  text "IMMERSION GOLD (ENIG)" at 12389.46,2726.92 h60
  text "ENEPIG" at 13727,2723.64 h60
  text "SURFACE FINISH:" at 11328.46,2722.64 h60
  text "X" at 12202.51,2722.64 h60
  text "IMM. TIN/SILVER OR EQUIV" at 11658,2565.64 h60
  text "OTHER" at 13089.46,2565.64 h60
  text "ARRAY/PANEL:" at 11328.46,2386.64 h60
  text "CUT AND TRIM PER M1 BOARD OUTLINE" at 12389.46,2382.35 h60
  text "N.C. ROUTE" at 12389.46,2230.64 h60
  text "X" at 13068.46,2230.64 h60
  text "V. SCORE" at 13255.46,2230.64 h60
  text "CERTIFICATION:" at 11328.46,2093.64 h60
  text "MATERIALS AND WORKMANSHIP FOR ALL PCBS" at 12053.46,2093.64 h60
  text "TO MEET OR EXCEED THE REQUIREMENTS OF:" at 12053.46,1995.64 h60
  text "X" at 11679.96,1859.13 h60
  text "ANSI IPC-A-600F CLASS ->" at 11818.96,1859.13 h60
  text "X" at 13458.02,1859.13 h60
  text "2" at 13576.96,1859.14 h60
  text "1" at 13261.96,1857.64 h60
  text "3" at 13930.96,1857.64 h60
  text "X" at 12494.02,1699.64 h60
  text "RoHS" at 12630.96,1699.64 h60
  text "OTHER" at 13275.36,1699.64 h60
  text "PER ORDER" at 13672.42,1699.64 h60
  text "ALL BOARDS MUST MEET OR EXCEED UL94-V0 REQUIREMENTS." at 11356,1534 h60
  text "PCB MUST BEAR THE UL94V-0 UL REGISTERED MATERIAL ID NUMBER" at 11356,1414 h60
  text "ADDITIONAL REQUIREMENTS:" at 11328.46,1240.64 h60
  text "MICROSECTION:" at 11403.23,1125.64 h60
  text "YES" at 12308.96,1125.64 h60
  text "REQUIRED" at 13170.46,969.49 h60
  text "BARE BOARD ELEC. TEST:" at 11403.23,966.64 h60
  text "NONE" at 12708.96,966.64 h60
  text "X" at 13043.46,966.64 h60
  text "PER ORDER" at 13762.46,966.64 h60
  text ".Layer_Name" at 577,-858.49 h60
  text ".Layer_Name" at 577,-858.49 h60
Mechanical 11:
  lines w10: -292,-930.17 6308,-930.17 ; -292,-726.83 6310,-726.83 ; -292,-523.5 -292,-1133.5 3713,-1133.5 6310,-1133.5 6310,-523.5 -291.5,-523.5 -291.5,-1133.5 1284,-1133.5 ; 2173,-1133.5 2173,-523.5 ; 3440,-726.83 3440,-523.5 ; 4280,-726.83 4280,-523.5 ; 4902,-1140 4902,-937.17
  text "ALL ARTWORK VIEWED FROM TOP SIDE" at -228.5,-655.67 h60
  text "BOARD #:" at 2248,-655.67 h60
  text ".PRJ_Number" at 2793.5,-655.67 h60
  text "REV:" at 3638,-655.67 h60
  text ".PCB_Rev" at 3929.5,-655.67 h60
  text "SVN REV:" at 4476,-655.67 h60
  text ".VersionControl_RevNumber" at 4982,-655.67 h60
  text "LAYER NAME =" at -228.5,-858.49 h60
  text "TID #:" at 2248,-859 h60
  text ".TID" at 2793.5,-859 h60
  text "PLOT NAME =" at -228.5,-1064.34 h60
  text ".plot_File_Name" at 577,-1064.34 h60
  text "GENERATED    :" at 2250,-1064.34 h60
  text ".Print_Date" at 3119.5,-1064.34 h60
  text ".Print_Time" at 3848.5,-1064.34 h60
  text "TEXAS INSTRUMENTS" at 5113,-1064.34 h60
Mechanical 12:
  drawing of 191 lines, arcs and shapes, not listed
  text "Layer" at 9790.58,7830 h60
  text "Name" at 10200.49,7830 h60
  text "Material" at 11130.23,7830 h60
  text "Thickness" at 11990,7830 h60
  text "Constant" at 12639.84,7830 h60
  text "Board Layer Stack" at 13209.7,7830 h60
  text "1" at 9790.58,7710 h60
  text "Top Overlay" at 10200.49,7710 h60
  text "2" at 9790.58,7590 h60
  text "Top Solder" at 10200.49,7590 h60
  text "Solder Resist" at 11130.23,7590 h60
  text "0.40mil" at 11990,7590 h60
  text "3.5" at 12639.84,7590 h60
  text "3" at 9790.58,7470 h60
  text "Top Layer" at 10200.49,7470 h60
  text "Copper" at 11130.23,7470 h60
  text "1.40mil" at 11990,7470 h60
  text "4" at 9790.58,7350 h60
  text "Dielectric1" at 10200.49,7350 h60
  text "FR-4" at 11130.23,7350 h60
  text "59.20mil" at 11990,7350 h60
  text "4.8" at 12639.84,7350 h60
  text "5" at 9790.58,7230 h60
  text "Bottom Layer" at 10200.49,7230 h60
  text "Copper" at 11130.23,7230 h60
  text "1.40mil" at 11990,7230 h60
  text "6" at 9790.58,7110 h60
  text "Bottom Solder" at 10200.49,7110 h60
  text "Solder Resist" at 11130.23,7110 h60
  text "0.40mil" at 11990,7110 h60
  text "3.5" at 12639.84,7110 h60
  text "7" at 9790.58,6990 h60
  text "Bottom Overlay" at 10200.49,6990 h60
  text ".Layer_Name" at 577,-858.49 h60
  text ".Layer_Name" at 577,-858.49 h60
Mechanical 13:
  text ".Layer_Name" at 577,-858.49 h60
  text ".Layer_Name" at 577,-858.49 h60
Mechanical 14:
  text ".Layer_Name" at 577,-858.49 h60
  text ".Layer_Name" at 577,-858.49 h60
Mechanical 15:
  text ".Layer_Name" at 577,-858.49 h60
  text ".Layer_Name" at 577,-858.49 h60
Mechanical 16:
  text ".Layer_Name" at 577,-858.49 h60
  text ".Layer_Name" at 577,-858.49 h60
Drill Drawing:
  text ".Layer_Name" at 577,-858.49 h60

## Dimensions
0,-400 to 1000,-400 on Mechanical 2
0,0 to 2400,0 on Mechanical 2
0,0 to 0,2000 on Mechanical 2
